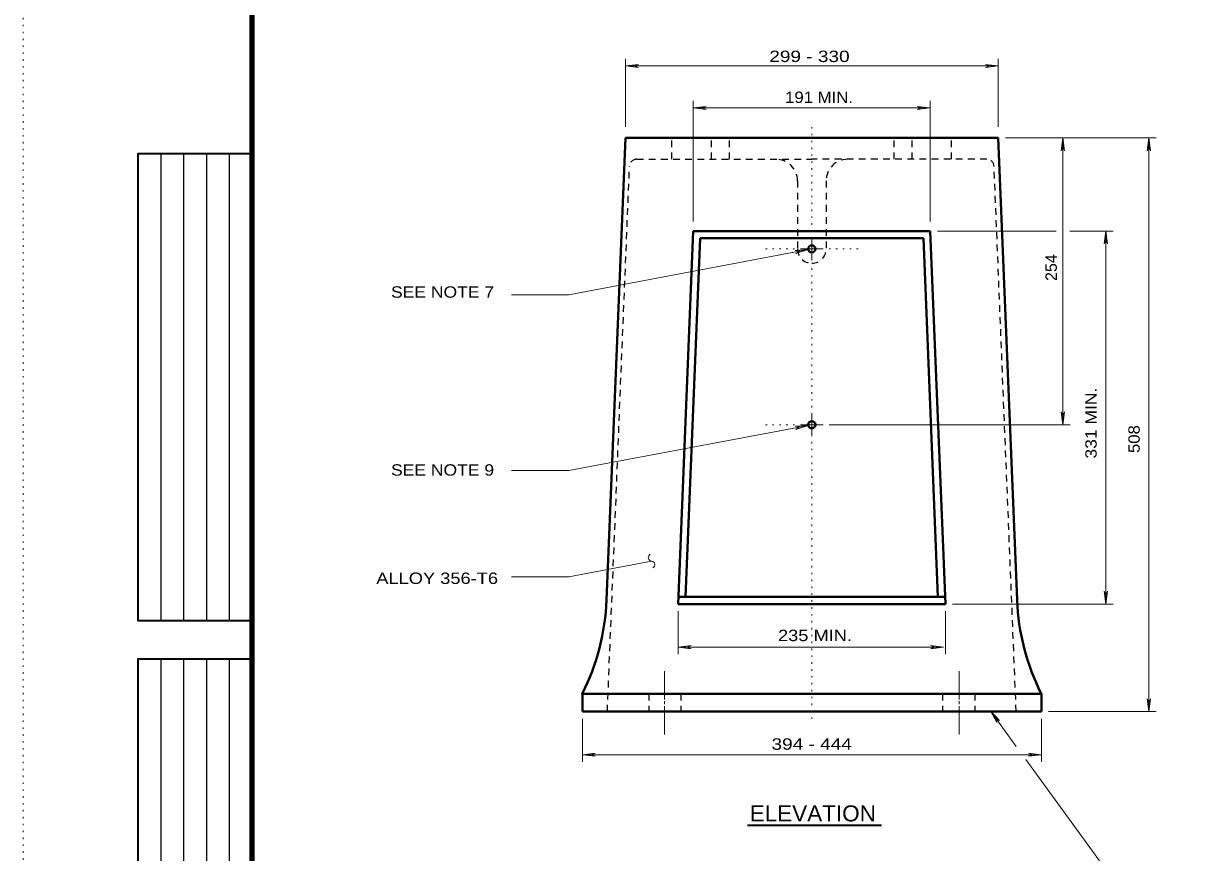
# Model space of a CAD drawing. Extents: x 312583 to 312854, y 144419 to 144597.
# Drawn here: x 312601.2 to 312678.9, y 144475.2 to 144530.6 of the extents above; entities that cross this region are included whole.
import ezdxf
from ezdxf.enums import TextEntityAlignment as Align

# ---------------------------------------------------------------- set-up
doc = ezdxf.new("R2010")
doc.units = 0
doc.header["$LTSCALE"] = 0.3
doc.linetypes.add('DOTTED', pattern=[1.5, 0.3, -1.2])
doc.linetypes.add('SHORT_DASHED', pattern=[2.7, 1.5, -1.2])
for name, color, linetype, lineweight in [('1', 7, 'Continuous', 40), ('2', 7, 'Continuous', 13), ('62', 7, 'DOTTED', 13)]:
    doc.layers.add(name, color=color, linetype=linetype, lineweight=lineweight)

msp = doc.modelspace()

# ---------------------------------------------------------------- linework, layer by layer
at = {"layer": '1'}
for p, q in [((312640.1717, 144492.0526), (312641.429, 144522.9263)), ((312653.8873, 144522.9263), (312641.429, 144522.9263)), ((312653.8873, 144522.9263), (312666.3457, 144522.9263)), ((312667.5953, 144492.0526), (312666.3457, 144522.9263)), ((312644.9557, 144491.7766), (312645.9677, 144516.6933)), ((312653.8873, 144516.6933), (312645.9677, 144516.6933)), ((312653.8873, 144516.6933), (312661.7993, 144516.6933)), ((312662.8113, 144491.7766), (312661.7993, 144516.6933)), ((312645.454, 144492.2596), (312646.4277, 144516.2179)), ((312653.8873, 144516.2179), (312646.4277, 144516.2179)), ((312653.8873, 144516.2179), (312661.3393, 144516.2179)), ((312662.313, 144492.2596), (312661.3393, 144516.2179)), ((312653.8873, 144492.2596), (312644.9787, 144492.2596)), ((312653.8873, 144492.2596), (312662.796, 144492.2596)), ((312653.8873, 144491.7766), (312644.9557, 144491.7766)), ((312653.8873, 144491.7766), (312662.8113, 144491.7766)), ((312638.554, 144485.7889), (312653.8873, 144485.7889)), ((312638.554, 144485.7889), (312638.554, 144484.5929)), ((312669.2207, 144485.7889), (312653.8873, 144485.7889)), ((312669.2207, 144485.7889), (312669.2207, 144484.5929)), ((312638.554, 144484.5929), (312653.8873, 144484.5929)), ((312669.2207, 144484.5929), (312653.8873, 144484.5929))]:
    msp.add_line(p, q, dxfattribs=at)
at = {"layer": '1', "linetype": 'SHORT_DASHED', "lineweight": 25}
for p, q in [((312644.5417, 144521.4849), (312644.5417, 144522.9263)), ((312647.179, 144521.4849), (312647.179, 144522.9263)), ((312648.375, 144521.4849), (312648.375, 144522.9263)), ((312659.392, 144521.4849), (312659.392, 144522.9263)), ((312660.5957, 144521.4849), (312660.5957, 144522.9263)), ((312663.2253, 144521.4849), (312663.2253, 144522.9263)), ((312640.2253, 144484.5929), (312641.705, 144521.0249)), ((312642.188, 144521.4849), (312653.8873, 144521.4849)), ((312665.579, 144521.4849), (312653.8873, 144521.4849)), ((312667.5417, 144484.5929), (312666.062, 144521.0249)), ((312652.929, 144520.0513), (312652.929, 144515.4973)), ((312654.8457, 144520.0513), (312654.8457, 144515.4973)), ((312642.9853, 144485.7889), (312642.9853, 144484.5929)), ((312645.1397, 144485.7889), (312645.1397, 144484.5929)), ((312662.6273, 144485.7889), (312662.6273, 144484.5929)), ((312664.7817, 144485.7889), (312664.7817, 144484.5929))]:
    msp.add_line(p, q, dxfattribs=at)
at = {"layer": '1', "lineweight": 25}
for p, q in [((312610.4087, 144490.6573), (312610.4087, 144521.8756)), ((312611.9315, 144490.6573), (312611.9315, 144521.8756)), ((312613.4543, 144490.6573), (312613.4543, 144521.8756)), ((312614.9772, 144490.6573), (312614.9772, 144521.8756)), ((312610.4087, 144456.901), (312610.4087, 144488.1192)), ((312611.9315, 144456.901), (312611.9315, 144488.1192)), ((312613.4543, 144456.901), (312613.4543, 144488.1192)), ((312614.9772, 144456.901), (312614.9772, 144488.1192))]:
    msp.add_line(p, q, dxfattribs=at)
at = {"layer": '1', "lineweight": 158}
msp.add_lwpolyline([(312616.5, 144423.1446), (312616.5, 144585.0846), (312849, 144585.0846)], dxfattribs=at)
at = {"layer": '1', "lineweight": 35}
for points in [[(312616.5, 144490.6573), (312608.8858, 144490.6573), (312608.8858, 144521.8756), (312616.5, 144521.8756)], [(312616.5, 144456.901), (312608.8858, 144456.901), (312608.8858, 144488.1192), (312616.5, 144488.1192)]]:
    msp.add_lwpolyline(points, dxfattribs=at)
at = {"layer": '1'}
for centre in [(312653.8835, 144515.4973), (312653.8835, 144515.4973), (312653.8835, 144503.7577), (312653.8835, 144503.7577)]:
    msp.add_circle(centre, 0.2396, dxfattribs=at)
at = {"layer": '1', "linetype": 'SHORT_DASHED', "lineweight": 25}
for centre, radius, start, end in [((312642.1859, 144521.0077), 0.4792, 90, 177.67414), ((312651.4877, 144520.0493), 1.4375, 0, 90), ((312656.2793, 144520.0493), 1.4375, 90, 180), ((312665.5811, 144521.0077), 0.4792, 2.32586, 90), ((312653.8835, 144515.4973), 0.9583, 180, 270), ((312653.8835, 144515.4973), 0.9583, 270, 0)]:
    msp.add_arc(centre, radius, start, end, dxfattribs=at)
at = {"layer": '1'}
for centre, start, end in [((312624.8513, 144492.6803), 333.30449, 357.6467), ((312682.9157, 144492.6803), 182.3533, 206.69551)]:
    msp.add_arc(centre, 15.3333, start, end, dxfattribs=at)
at = {"layer": '2'}
for p, q in [((312641.429, 144523.6546), (312641.429, 144528.1933)), ((312666.3457, 144523.6546), (312666.3457, 144528.1933)), ((312641.429, 144527.7179), (312642.2953, 144527.8253)), ((312641.429, 144527.7179), (312666.3457, 144527.7179)), ((312641.429, 144527.7179), (312642.2953, 144527.6106)), ((312642.2953, 144527.8253), (312642.0193, 144527.7179)), ((312642.2953, 144527.6106), (312642.0193, 144527.7179)), ((312665.4793, 144527.8253), (312665.7553, 144527.7179)), ((312666.3457, 144527.7179), (312665.4793, 144527.8253)), ((312665.4793, 144527.6106), (312665.7553, 144527.7179)), ((312666.3457, 144527.7179), (312665.4793, 144527.6106)), ((312645.9677, 144517.3296), (312645.9677, 144525.3873)), ((312645.9677, 144524.9119), (312646.834, 144525.0193)), ((312645.9677, 144524.9119), (312661.7993, 144524.9119)), ((312645.9677, 144524.9119), (312646.834, 144524.8046)), ((312646.834, 144525.0193), (312646.558, 144524.9119)), ((312646.834, 144524.8046), (312646.558, 144524.9119)), ((312660.933, 144525.0193), (312661.209, 144524.9119)), ((312661.7993, 144524.9119), (312660.933, 144525.0193)), ((312660.933, 144524.8046), (312661.209, 144524.9119)), ((312661.7993, 144524.9119), (312660.933, 144524.8046)), ((312661.7993, 144517.3296), (312661.7993, 144525.3873)), ((312666.821, 144522.9263), (312676.8873, 144522.9263)), ((312670.6543, 144522.9263), (312670.547, 144522.0599)), ((312670.6543, 144503.7596), (312670.6543, 144522.9263)), ((312670.6543, 144522.9263), (312670.7617, 144522.0599)), ((312676.4043, 144522.9263), (312676.297, 144522.0599)), ((312676.4043, 144484.5929), (312676.4043, 144522.9263)), ((312676.4043, 144522.9263), (312676.5117, 144522.0599)), ((312670.547, 144522.0599), (312670.6543, 144522.3359)), ((312670.7617, 144522.0599), (312670.6543, 144522.3359)), ((312676.297, 144522.0599), (312676.4043, 144522.3359)), ((312676.5117, 144522.0599), (312676.4043, 144522.3359)), ((312653.8873, 144515.4973), (312653.8873, 144516.2639)), ((312662.2823, 144516.6933), (312670.2097, 144516.6933)), ((312671.122, 144516.6933), (312674.0123, 144516.6933)), ((312673.5293, 144516.6933), (312673.422, 144515.8269)), ((312673.5293, 144491.7766), (312673.5293, 144516.6933)), ((312673.5293, 144516.6933), (312673.6367, 144515.8269)), ((312653.8873, 144515.4973), (312653.1207, 144515.4973)), ((312653.8873, 144515.4973), (312654.654, 144515.4973)), ((312653.8873, 144515.4973), (312653.8873, 144514.7306)), ((312673.422, 144515.8269), (312673.5293, 144516.1029)), ((312673.6367, 144515.8269), (312673.5293, 144516.1029)), ((312653.6497, 144515.4513), (312637.6493, 144512.4383)), ((312653.6497, 144515.4513), (312652.7757, 144515.3976)), ((312652.7757, 144515.3976), (312653.067, 144515.3439)), ((312653.6497, 144515.4513), (312652.814, 144515.1906)), ((312652.814, 144515.1906), (312653.067, 144515.3439)), ((312637.6493, 144512.4383), (312633.816, 144512.4383)), ((312670.547, 144504.6259), (312670.6543, 144504.3499)), ((312670.6543, 144503.7596), (312670.547, 144504.6259)), ((312670.7617, 144504.6259), (312670.6543, 144504.3499)), ((312670.6543, 144503.7596), (312670.7617, 144504.6259)), ((312653.8873, 144503.7596), (312653.8873, 144504.5263)), ((312653.6497, 144503.7136), (312637.6493, 144500.6929)), ((312653.6497, 144503.7136), (312652.7757, 144503.6599)), ((312652.7757, 144503.6599), (312653.067, 144503.6063)), ((312653.6497, 144503.7136), (312652.814, 144503.4453)), ((312652.814, 144503.4453), (312653.067, 144503.6063)), ((312653.8873, 144503.7596), (312653.1207, 144503.7596)), ((312653.8873, 144503.7596), (312653.8873, 144502.9929)), ((312653.8873, 144503.7596), (312654.654, 144503.7596)), ((312655.0373, 144503.7596), (312671.1373, 144503.7596)), ((312637.6493, 144500.6929), (312633.816, 144500.6929)), ((312643.1847, 144494.6516), (312637.6493, 144493.6013)), ((312637.6493, 144493.6013), (312633.816, 144493.6013)), ((312673.422, 144492.6429), (312673.5293, 144492.3669)), ((312673.5293, 144491.7766), (312673.422, 144492.6429)), ((312673.6367, 144492.6429), (312673.5293, 144492.3669)), ((312673.5293, 144491.7766), (312673.6367, 144492.6429)), ((312663.2943, 144491.7766), (312674.0123, 144491.7766)), ((312644.9557, 144491.3013), (312644.9557, 144488.4263)), ((312662.8113, 144491.3013), (312662.8113, 144488.4263)), ((312644.9557, 144488.9016), (312645.822, 144489.0089)), ((312644.9557, 144488.9016), (312662.6887, 144488.9016)), ((312644.9557, 144488.9016), (312645.822, 144488.7943)), ((312645.822, 144489.0089), (312645.546, 144488.9016)), ((312645.822, 144488.7943), (312645.546, 144488.9016)), ((312661.8223, 144489.0089), (312662.0983, 144488.9016)), ((312662.6887, 144488.9016), (312661.8223, 144489.0089)), ((312661.8223, 144488.7943), (312662.0983, 144488.9016)), ((312662.6887, 144488.9016), (312661.8223, 144488.7943)), ((312644.0433, 144485.4056), (312644.0433, 144487.2916)), ((312663.7237, 144485.4056), (312663.7237, 144487.2916)), ((312644.0433, 144485.0913), (312644.0433, 144485.2829)), ((312663.7237, 144485.0913), (312663.7237, 144485.2829)), ((312676.297, 144485.4593), (312676.4043, 144485.1833)), ((312676.4043, 144484.5929), (312676.297, 144485.4593)), ((312676.5117, 144485.4593), (312676.4043, 144485.1833)), ((312676.4043, 144484.5929), (312676.5117, 144485.4593)), ((312644.0433, 144484.9686), (312644.0433, 144483.0749)), ((312663.7237, 144484.9686), (312663.7237, 144483.0749)), ((312667.5493, 144482.2546), (312665.8167, 144484.6389)), ((312665.8167, 144484.6389), (312666.2383, 144483.8723)), ((312665.8167, 144484.6389), (312666.4147, 144484.0026)), ((312669.696, 144484.5929), (312676.8873, 144484.5929)), ((312638.554, 144481.2349), (312638.554, 144484.1099)), ((312666.2383, 144483.8723), (312666.1617, 144484.1636)), ((312666.4147, 144484.0026), (312666.1617, 144484.1636)), ((312669.2207, 144481.2349), (312669.2207, 144484.1099)), ((312638.554, 144481.7179), (312639.4203, 144481.8253)), ((312638.554, 144481.7179), (312669.2207, 144481.7179)), ((312638.554, 144481.7179), (312639.4203, 144481.6106)), ((312639.4203, 144481.8253), (312639.1443, 144481.7179)), ((312639.4203, 144481.6106), (312639.1443, 144481.7179)), ((312673.5293, 144474.0513), (312668.178, 144481.4036)), ((312668.3543, 144481.8253), (312668.6303, 144481.7179)), ((312669.2207, 144481.7179), (312668.3543, 144481.8253)), ((312668.3543, 144481.6106), (312668.6303, 144481.7179)), ((312669.2207, 144481.7179), (312668.3543, 144481.6106))]:
    msp.add_line(p, q, dxfattribs=at)
at = {"layer": '2', "linetype": 'DOTTED'}
for p, q in [((312653.8873, 144516.6473), (312653.8873, 144523.6239)), ((312652.7373, 144515.4973), (312650.4603, 144515.4973)), ((312655.0373, 144515.4973), (312656.9847, 144515.4973)), ((312653.8873, 144504.9096), (312653.8873, 144514.4316)), ((312652.7373, 144503.7596), (312650.4603, 144503.7596)), ((312653.8873, 144502.6096), (312653.8873, 144483.7726))]:
    msp.add_line(p, q, dxfattribs=at)
at = {"layer": '2', "lineweight": 35}
msp.add_line((312649.581, 144477.0106), (312658.5491, 144477.0106), dxfattribs=at)
at = {"layer": '2'}
for centre, start, end in [((312643.1988, 144494.8866), 115.69034, 265.69034), ((312643.1628, 144494.409), 295.69034, 85.69034)]:
    msp.add_arc(centre, 0.2395, start, end, dxfattribs=at)
at = {"layer": '62'}
msp.add_line((312601.2, 144418.5846), (312601.2, 144596.7846), dxfattribs=at)

# ---------------------------------------------------------------- texts
at = {"layer": '2'}
for s, width, p in [('299 - 330', 1.25, (312651.0434, 144527.9792)), ('191 MIN.', 1.1, (312652.1006, 144525.2434)), ('SEE NOTE 7', 1.15, (312625.7717, 144512.2396)), ('SEE NOTE 9', 1.15, (312625.7713, 144500.3539)), ('ALLOY 356-T6', 1.2, (312624.7869, 144493.1219)), ('235 MIN.', 1.2, (312651.6245, 144489.3032)), ('394 - 444', 1.25, (312651.1923, 144482.0494))]:
    msp.add_text(s, height=0.76, dxfattribs=dict(at, width=width)).set_placement(p)
for s, width, p in [('254', 1.05, (312670.2561, 144513.3597)), ('331 MIN.', 1.15, (312672.9185, 144501.4956)), ('508', 1.1, (312675.7934, 144501.8638))]:
    msp.add_text(s, height=0.76, rotation=90, dxfattribs=dict(at, width=width)).set_placement(p)
at = {"layer": '2', "width": 1.05}
msp.add_text('ELEVATION', height=1.07, dxfattribs=at).set_placement((312653.9509, 144477.2622), align=Align.CENTER)

doc.saveas('drawing.dxf')
